Omron CX-Programmer project 新工程 (CX-Programmer 9.50)

# PLC 新PLC1: CP1H X

## Global symbols (name address type ; comment)
0 CHANNEL  ; 重复
1 CHANNEL  ; 完成
1635 CHANNEL  ; 要校验数据开始地址
A392.05 BOOL  ; 串口2就绪
A392.06 BOOL  ; 串口2接收完成
A393 CHANNEL  ; 接收计数器
A526.00 BOOL  ; 复位串口2
D1000 CHANNEL  ; 发送控制字
D1001 CHANNEL  ; 发送字节数
D1002 CHANNEL  ; 站号、功能码
D1003 CHANNEL  ; 寄存器开始地址
D1004 CHANNEL  ; 数据量
D1300 CHANNEL  ; 控制数据
D1301 CHANNEL  ; 收回的字节数
D1315 CHANNEL  ; 备份写数据
D1600 CHANNEL  ; 温度PV首地址
D1605 CHANNEL  ; 输出限位手动参数地址
D1610 CHANNEL  ; 检查结果0
D1611 CHANNEL  ; 检查结果1
D1612 CHANNEL  ; 检查结果2
D1613 CHANNEL  ; 检查结果3
D1614 CHANNEL  ; 检查结果4
D1615 CHANNEL  ; 检查结果5
D1616 CHANNEL  ; 检查结果6
D1617 CHANNEL  ; 结果2
D1618 CHANNEL  ; 缓存
D1619 CHANNEL  ; 检查中止操作位
D1620 CHANNEL  ; 通道
D1621 CHANNEL  ; 缓存
D1622 CHANNEL  ; 缓存
D1623 CHANNEL  ; 数据一致
D1624 CHANNEL  ; 比较开始地址1
D1625 CHANNEL  ; 比较开始地址2
D1626 CHANNEL  ; 比较结果地址
D1627 CHANNEL  ; 比较结果2
D1628 CHANNEL  ; 比较结果3
D1629 CHANNEL  ; 比较结果4
D1630 CHANNEL  ; 通信状态
D1631 CHANNEL  ; 模块类型
D1632 CHANNEL  ; 延时计数
D1633 CHANNEL  ; 通信故障计数器
D1634 CHANNEL  ; 要校验数据长度
D1635 CHANNEL  ; 要校验的数据首地址
D1636 CHANNEL  ; CRC高字节
D1637 CHANNEL  ; CRC低字节
D1638 CHANNEL  ; CRC结果
D1640 CHANNEL  ; 启动控制地址
D1641 CHANNEL  ; 启动控制缓存地址
D1642 CHANNEL  ; 通信计数器地址
D1643 CHANNEL  ; 故障计数器地址
D1644 CHANNEL  ; 通信计数器地址
D1645 CHANNEL  ; 通信故障计数器地址
D1646 CHANNEL  ; SV缓存首地址
D1647 CHANNEL  ; Pb缓存首地址
D1648 CHANNEL  ; 启动停止缓存地址
D1649 CHANNEL  ; 整定缓存地址
D1650 CHANNEL  ; 模块站号
D1651 CHANNEL  ; 参数开始地址
D1652 CHANNEL  ; 通信错误码
D1653 CHANNEL  ; 站切换状态
D1654 CHANNEL  ; 间隔计数
D1956 CHANNEL  ; 指针1
D1957 CHANNEL  ; 指针2
D1958 CHANNEL  ; 计数
D1960 CHANNEL  ; 缓存
D1961 CHANNEL  ; 计算的字节
D1962 CHANNEL  ; 高字节
D20000 CHANNEL  ; 发送控制字
D20001 CHANNEL  ; 发送字节数
D20002 CHANNEL  ; 站号、功能码
D20003 CHANNEL  ; 开始地址
D20004 CHANNEL  ; 字数
D20138 CHANNEL  ; CRC结果
D20300 CHANNEL  ; 控制数据
D20301 CHANNEL  ; 收回的字节数
D20315 CHANNEL  ; 备份数据
D20610 CHANNEL  ; 比较结果1
D20611 CHANNEL  ; 比较结果2
D20612 CHANNEL  ; 比较结果3
D20623 CHANNEL  ; 数据一致
D20624 CHANNEL  ; 比较开始地址1
D20625 CHANNEL  ; 比较开始地址2
D20630 CHANNEL  ; 通信状态
D20632 CHANNEL  ; 延时计数
D20633 CHANNEL  ; 通信故障计数
D20634 CHANNEL  ; 校验数据长度
D20635 CHANNEL  ; 校验数据源地址
D20636 CHANNEL  ; CRC高字节
D20637 CHANNEL  ; CRC低字节
D20638 CHANNEL  ; CRC结果
D20640 CHANNEL  ; 启停参数地址
D20641 CHANNEL  ; 启停参数缓存地址
D20642 CHANNEL  ; 通信计数地址
D20643 CHANNEL  ; 通信故障计数地址
D20650 CHANNEL  ; 站号变量
D20651 CHANNEL  ; 数据存放变量
D20653 CHANNEL  ; 站号切换状态
D20654 CHANNEL  ; 通信间隔
D20655 CHANNEL  ; 缓存
D2074 CHANNEL  ; 模块1读Pb记录
D20956 CHANNEL  ; 指针1
D20957 CHANNEL  ; 指针2
D20958 CHANNEL  ; 计数
D20960 CHANNEL  ; 缓存
D20961 CHANNEL  ; 计算的字节
D2274 CHANNEL  ; 模块2读Pb记录
T0200 BOOL  ; 读温度超时
T0201 BOOL  ; 读输出限位超时
T0202 BOOL  ; 写参数超时
T0203 BOOL  ; 写手动、输出限位超时
T0204 BOOL  ; 写整定超时
W20.00 BOOL  ; CRC校验错误
W20.01 BOOL  ; 读输出CRC错误
W20.02 BOOL  ; 写模块校验错误
W20.10 BOOL  ; 通信完成
W21.00 BOOL  ; 启动通信
W22.00 BOOL  ; 发送读温度消息
W22.01 BOOL  ; 发送写参数消息
W22.02 BOOL  ; 发整定消息
W22.03 BOOL  ; 发送读Pb消息
W22.04 BOOL  ; 发送写Pb消息
W22.05 BOOL  ; 接收数据处理
W22.06 BOOL  ; 发送写参数消息
W22.07 BOOL  ; 检查接收是否完成
W22.08 BOOL  ; 接收数据处理
W22.09 BOOL  ; 写手动输出准备
W22.10 BOOL  ; 检查接收完成
W22.11 BOOL  ; 接收数据处理
W22.12 BOOL  ; 写手动输出限位
W22.13 BOOL  ; 检查接收完成
W22.14 BOOL  ; 接收数据处理

## Program BD4543通信 (cyclic task 0)
Local symbols
CRC余数表 D1700 WORD  ; CRC余数表
的630 UINT

### Section 调信主程序

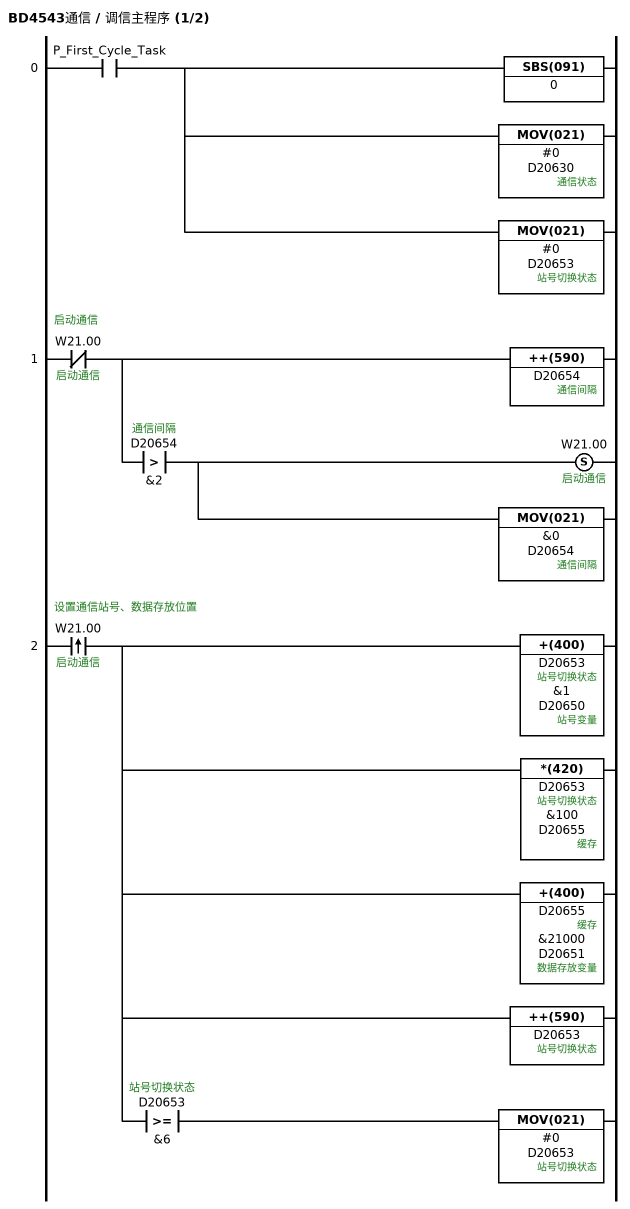
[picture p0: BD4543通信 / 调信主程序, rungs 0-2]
; rung 0
LD P_First_Cycle_Task
SBS(091) 0  // 初始化
MOV(021) #0 D20630  ; 通信状态
MOV(021) #0 D20653  ; 站号切换状态
; rung 1: 启动通信
LDNOT W21.00  ; 启动通信
++(590) D20654  ; 通信间隔
AND>(320) D20654 &2  ; 通信间隔
SET W21.00  ; 启动通信
MOV(021) &0 D20654  ; 通信间隔
; rung 2: 设置通信站号、数据存放位置
@LD W21.00  ; 启动通信
+(400) D20653 &1 D20650  ; 站号切换状态, 站号变量
*(420) D20653 &100 D20655  ; 站号切换状态, 缓存
+(400) D20655 &21000 D20651  ; 缓存, 数据存放变量
++(590) D20653  ; 站号切换状态
AND>=(325) D20653 &6  ; 站号切换状态
MOV(021) #0 D20653  ; 站号切换状态

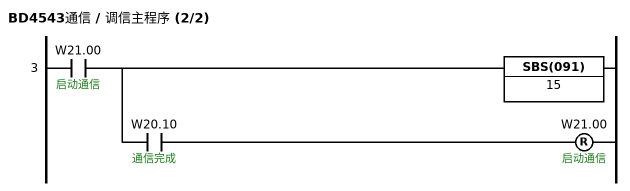
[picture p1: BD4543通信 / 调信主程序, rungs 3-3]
; rung 3
LD W21.00  ; 启动通信
SBS(091) 15
AND W20.10  ; 通信完成
RSET W21.00  ; 启动通信

### Section 通信状态处理15

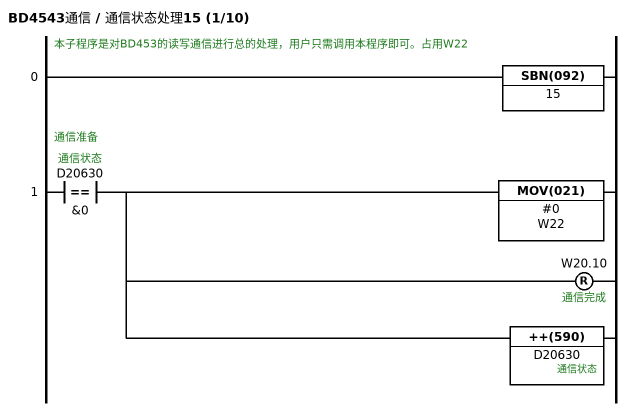
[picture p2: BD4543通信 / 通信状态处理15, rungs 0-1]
; rung 0: 本子程序是对BD453的读写通信进行总的处理，用户只需调用本程序即可。占用W22
SBN(092) 15
; rung 1: 通信准备
LD=(300) D20630 &0  ; 通信状态
MOV(021) #0 W22
RSET W20.10  ; 通信完成
++(590) D20630  ; 通信状态

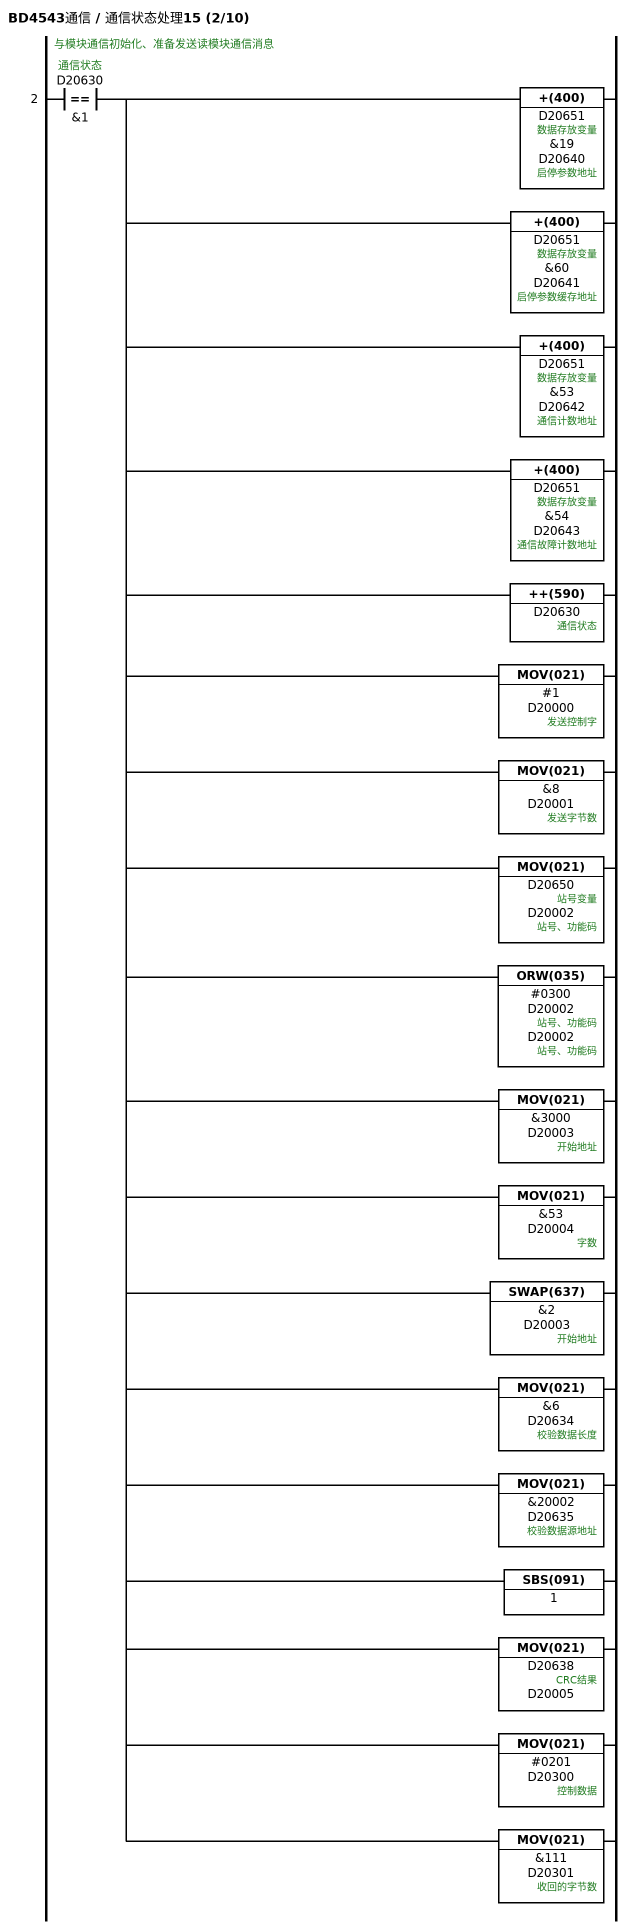
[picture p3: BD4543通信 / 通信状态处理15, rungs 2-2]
; rung 2: 与模块通信初始化、准备发送读模块通信消息
LD=(300) D20630 &1  ; 通信状态
+(400) D20651 &19 D20640  ; 数据存放变量, 启停参数地址
+(400) D20651 &60 D20641  ; 数据存放变量, 启停参数缓存地址
+(400) D20651 &53 D20642  ; 数据存放变量, 通信计数地址
+(400) D20651 &54 D20643  ; 数据存放变量, 通信故障计数地址
++(590) D20630  ; 通信状态
MOV(021) #1 D20000  ; 发送控制字
MOV(021) &8 D20001  ; 发送字节数
MOV(021) D20650 D20002  ; 站号变量, 站号、功能码
ORW(035) #0300 D20002 D20002  ; 站号、功能码
MOV(021) &3000 D20003  ; 开始地址
MOV(021) &53 D20004  ; 字数
SWAP(637) &2 D20003  ; 开始地址
MOV(021) &6 D20634  ; 校验数据长度
MOV(021) &20002 D20635  ; 校验数据源地址
SBS(091) 1
MOV(021) D20638 D20005  ; CRC结果
MOV(021) #0201 D20300  ; 控制数据
MOV(021) &111 D20301  ; 收回的字节数

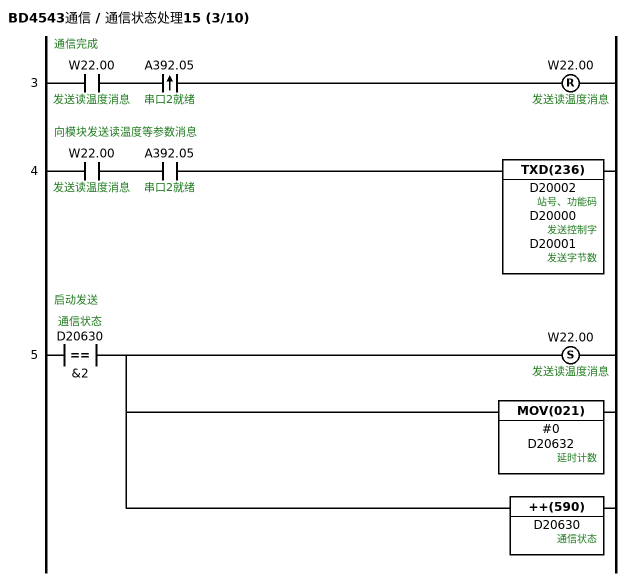
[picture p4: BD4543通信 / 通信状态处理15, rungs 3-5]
; rung 3: 通信完成
LD W22.00  ; 发送读温度消息
@AND A392.05  ; 串口2就绪
RSET W22.00  ; 发送读温度消息
; rung 4: 向模块发送读温度等参数消息
LD W22.00  ; 发送读温度消息
AND A392.05  ; 串口2就绪
TXD(236) D20002 D20000 D20001  ; 站号、功能码, 发送控制字, 发送字节数
; rung 5: 启动发送
LD=(300) D20630 &2  ; 通信状态
SET W22.00  ; 发送读温度消息
MOV(021) #0 D20632  ; 延时计数
++(590) D20630  ; 通信状态

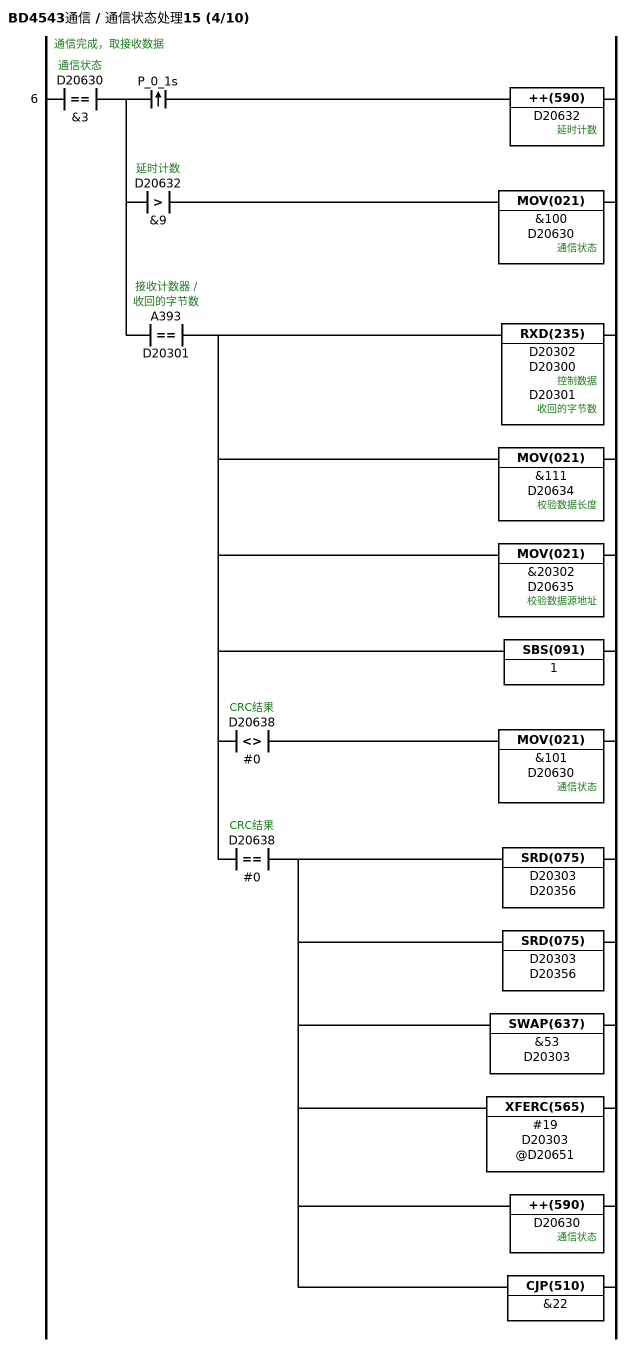
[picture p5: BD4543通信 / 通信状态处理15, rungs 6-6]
; rung 6: 通信完成，取接收数据
LD=(300) D20630 &3  ; 通信状态
OUT TR0
@AND P_0_1s
++(590) D20632  ; 延时计数
LD TR0
AND>(320) D20632 &9  ; 延时计数
MOV(021) &100 D20630  ; 通信状态
LD TR0
AND=(300) A393 D20301  ; 接收计数器, 收回的字节数
OUT TR0
RXD(235) D20302 D20300 D20301  ; 控制数据, 收回的字节数
MOV(021) &111 D20634  ; 校验数据长度
MOV(021) &20302 D20635  ; 校验数据源地址
SBS(091) 1
AND<>(305) D20638 #0  ; CRC结果
MOV(021) &101 D20630  ; 通信状态
LD TR0
AND=(300) D20638 #0  ; CRC结果
SRD(075) D20303 D20356
SRD(075) D20303 D20356
SWAP(637) &53 D20303
XFERC(565) #19 D20303 @D20651
++(590) D20630  ; 通信状态
CJP(510) &22

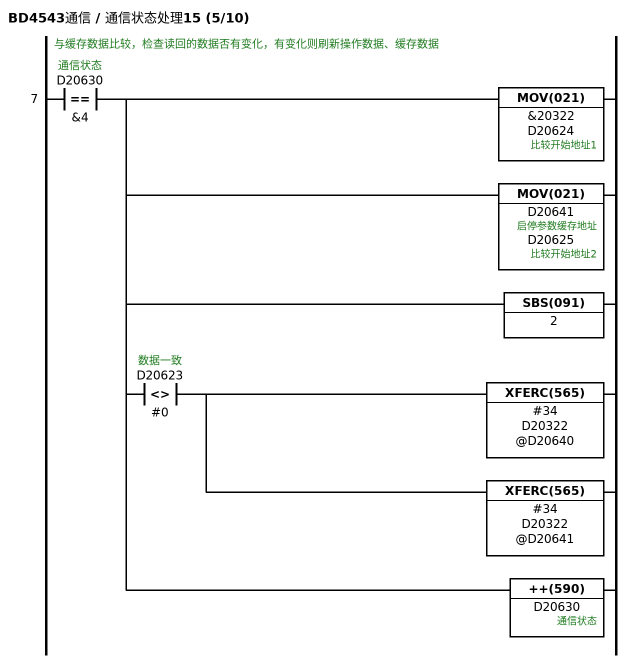
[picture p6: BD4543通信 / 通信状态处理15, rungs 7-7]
; rung 7: 与缓存数据比较，检查读回的数据否有变化，有变化则刷新操作数据、缓存数据
LD=(300) D20630 &4  ; 通信状态
OUT TR0
MOV(021) &20322 D20624  ; 比较开始地址1
MOV(021) D20641 D20625  ; 启停参数缓存地址, 比较开始地址2
SBS(091) 2
AND<>(305) D20623 #0  ; 数据一致
XFERC(565) #34 D20322 @D20640
XFERC(565) #34 D20322 @D20641
LD TR0
++(590) D20630  ; 通信状态

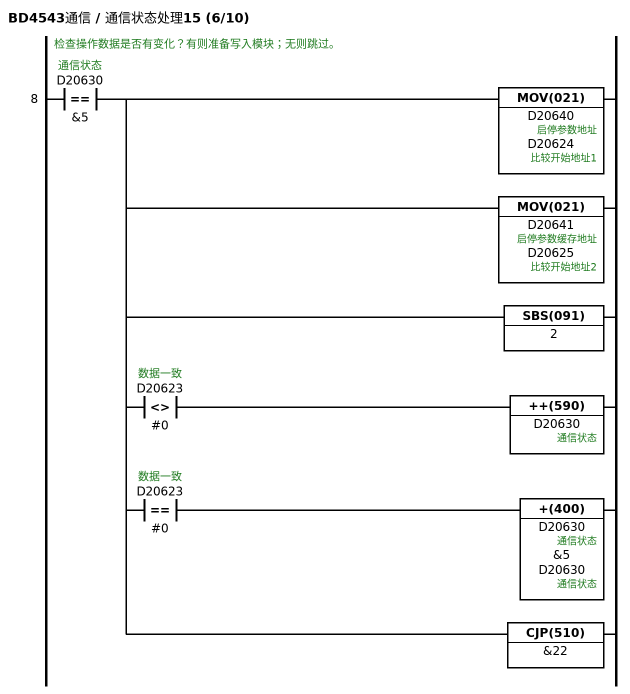
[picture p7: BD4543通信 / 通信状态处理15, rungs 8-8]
; rung 8: 检查操作数据是否有变化？有则准备写入模块；无则跳过。
LD=(300) D20630 &5  ; 通信状态
OUT TR0
MOV(021) D20640 D20624  ; 启停参数地址, 比较开始地址1
MOV(021) D20641 D20625  ; 启停参数缓存地址, 比较开始地址2
SBS(091) 2
AND<>(305) D20623 #0  ; 数据一致
++(590) D20630  ; 通信状态
LD TR0
AND=(300) D20623 #0  ; 数据一致
+(400) D20630 &5 D20630  ; 通信状态
LD TR0
CJP(510) &22

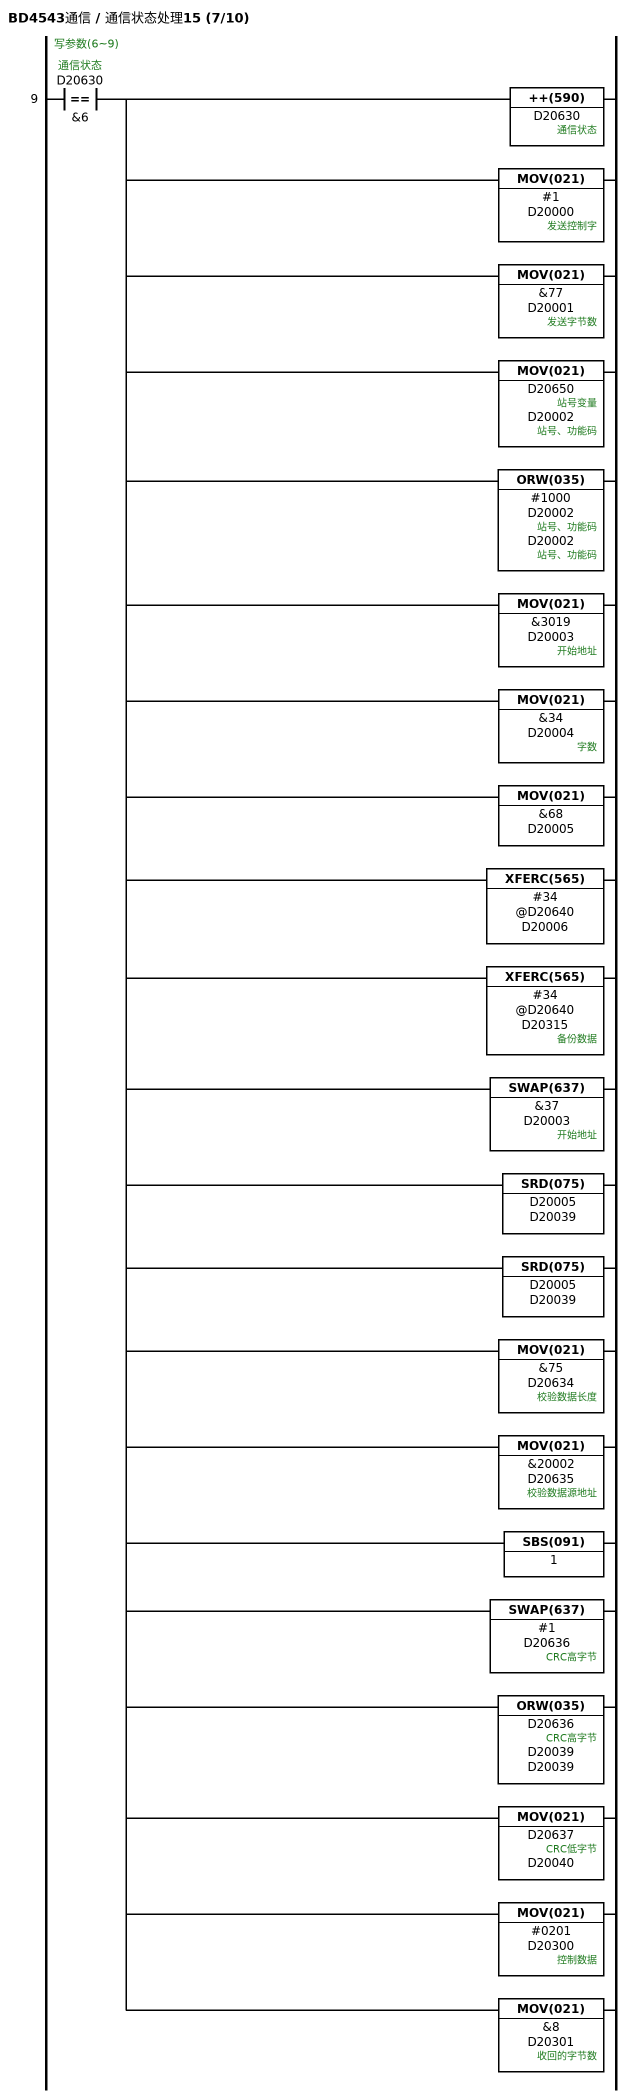
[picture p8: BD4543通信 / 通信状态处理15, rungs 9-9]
; rung 9: 写参数(6~9)
LD=(300) D20630 &6  ; 通信状态
++(590) D20630  ; 通信状态
MOV(021) #1 D20000  ; 发送控制字
MOV(021) &77 D20001  ; 发送字节数
MOV(021) D20650 D20002  ; 站号变量, 站号、功能码
ORW(035) #1000 D20002 D20002  ; 站号、功能码
MOV(021) &3019 D20003  ; 开始地址
MOV(021) &34 D20004  ; 字数
MOV(021) &68 D20005
XFERC(565) #34 @D20640 D20006
XFERC(565) #34 @D20640 D20315  ; 备份数据
SWAP(637) &37 D20003  ; 开始地址
SRD(075) D20005 D20039
SRD(075) D20005 D20039
MOV(021) &75 D20634  ; 校验数据长度
MOV(021) &20002 D20635  ; 校验数据源地址
SBS(091) 1
SWAP(637) #1 D20636  ; CRC高字节
ORW(035) D20636 D20039 D20039  ; CRC高字节
MOV(021) D20637 D20040  ; CRC低字节
MOV(021) #0201 D20300  ; 控制数据
MOV(021) &8 D20301  ; 收回的字节数

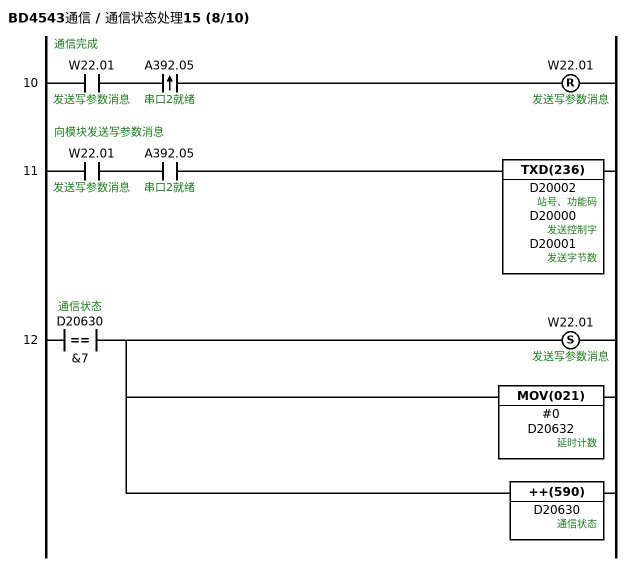
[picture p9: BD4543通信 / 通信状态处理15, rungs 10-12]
; rung 10: 通信完成
LD W22.01  ; 发送写参数消息
@AND A392.05  ; 串口2就绪
RSET W22.01  ; 发送写参数消息
; rung 11: 向模块发送写参数消息
LD W22.01  ; 发送写参数消息
AND A392.05  ; 串口2就绪
TXD(236) D20002 D20000 D20001  ; 站号、功能码, 发送控制字, 发送字节数
; rung 12
LD=(300) D20630 &7  ; 通信状态
SET W22.01  ; 发送写参数消息
MOV(021) #0 D20632  ; 延时计数
++(590) D20630  ; 通信状态

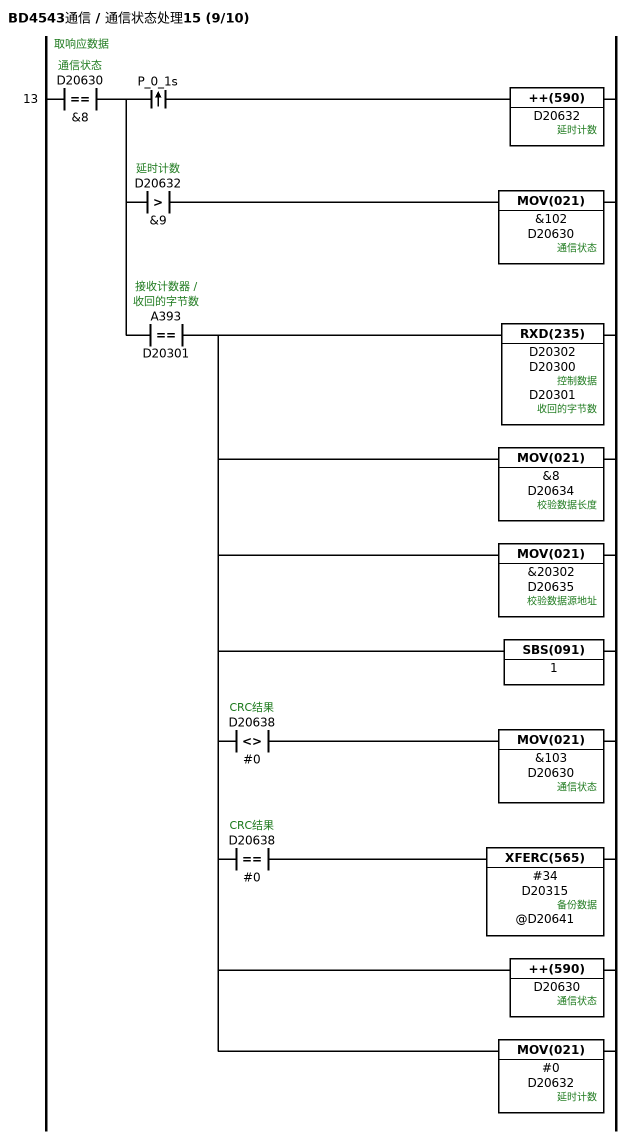
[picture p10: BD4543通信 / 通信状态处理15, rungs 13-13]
; rung 13: 取响应数据
LD=(300) D20630 &8  ; 通信状态
OUT TR0
@AND P_0_1s
++(590) D20632  ; 延时计数
LD TR0
AND>(320) D20632 &9  ; 延时计数
MOV(021) &102 D20630  ; 通信状态
LD TR0
AND=(300) A393 D20301  ; 接收计数器, 收回的字节数
OUT TR0
RXD(235) D20302 D20300 D20301  ; 控制数据, 收回的字节数
MOV(021) &8 D20634  ; 校验数据长度
MOV(021) &20302 D20635  ; 校验数据源地址
SBS(091) 1
AND<>(305) D20638 #0  ; CRC结果
MOV(021) &103 D20630  ; 通信状态
LD TR0
AND=(300) D20638 #0  ; CRC结果
XFERC(565) #34 D20315 @D20641  ; 备份数据
LD TR0
++(590) D20630  ; 通信状态
MOV(021) #0 D20632  ; 延时计数

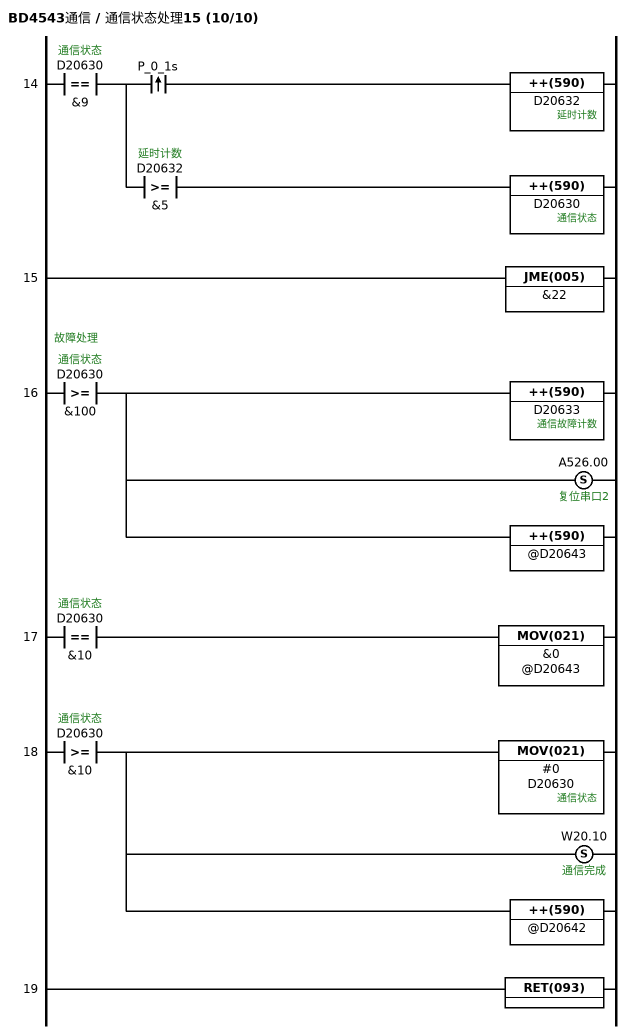
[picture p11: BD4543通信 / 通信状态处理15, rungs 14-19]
; rung 14
LD=(300) D20630 &9  ; 通信状态
OUT TR0
@AND P_0_1s
++(590) D20632  ; 延时计数
LD TR0
AND>=(325) D20632 &5  ; 延时计数
++(590) D20630  ; 通信状态
; rung 15
JME(005) &22
; rung 16: 故障处理
LD>=(325) D20630 &100  ; 通信状态
++(590) D20633  ; 通信故障计数
SET A526.00  ; 复位串口2
++(590) @D20643
; rung 17
LD=(300) D20630 &10  ; 通信状态
MOV(021) &0 @D20643
; rung 18
LD>=(325) D20630 &10  ; 通信状态
MOV(021) #0 D20630  ; 通信状态
SET W20.10  ; 通信完成
++(590) @D20642
; rung 19
RET(093)

### Section 通信初始化0

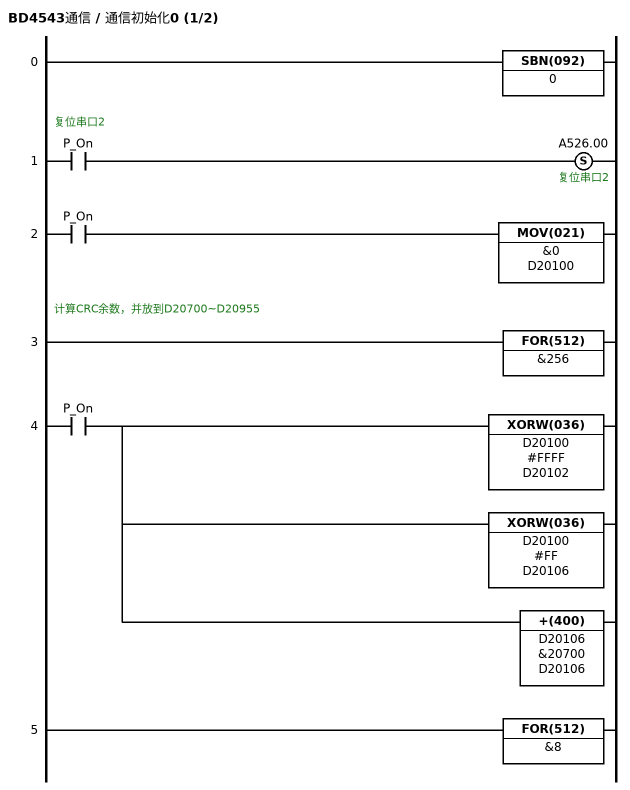
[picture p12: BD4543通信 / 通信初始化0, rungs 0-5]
; rung 0
SBN(092) 0
; rung 1: 复位串口2
LD P_On
SET A526.00  ; 复位串口2
; rung 2
LD P_On
MOV(021) &0 D20100
; rung 3: 计算CRC余数，并放到D20700~D20955
FOR(512) &256
; rung 4
LD P_On
XORW(036) D20100 #FFFF D20102
XORW(036) D20100 #FF D20106
+(400) D20106 &20700 D20106
; rung 5
FOR(512) &8

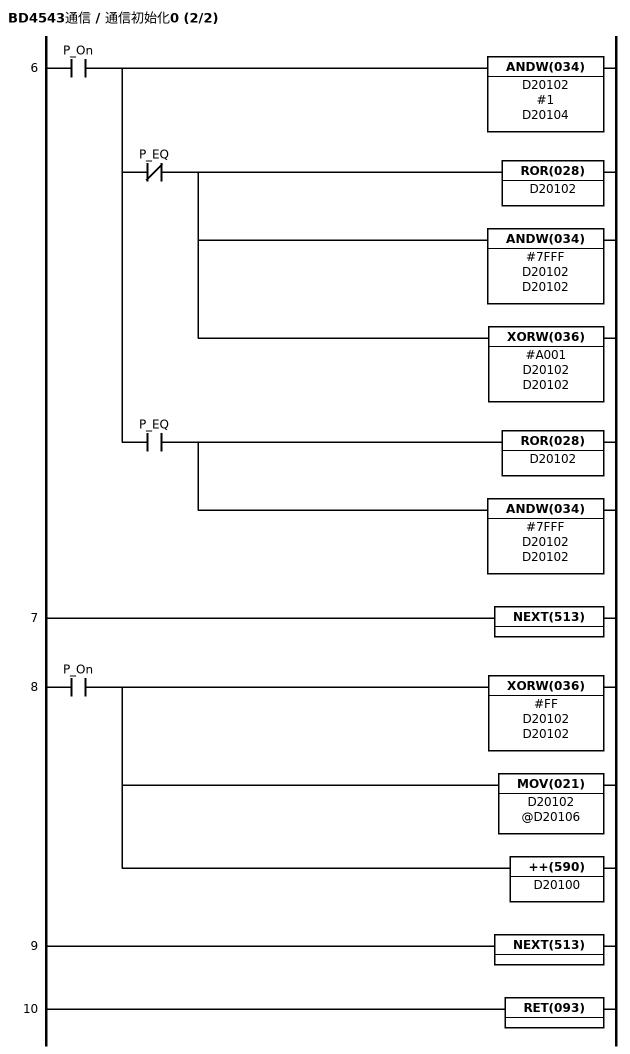
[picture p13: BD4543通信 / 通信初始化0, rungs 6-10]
; rung 6
LD P_On
OUT TR0
ANDW(034) D20102 #1 D20104
ANDNOT P_EQ
ROR(028) D20102
ANDW(034) #7FFF D20102 D20102
XORW(036) #A001 D20102 D20102
LD TR0
AND P_EQ
ROR(028) D20102
ANDW(034) #7FFF D20102 D20102
; rung 7
NEXT(513)
; rung 8
LD P_On
XORW(036) #FF D20102 D20102
MOV(021) D20102 @D20106
++(590) D20100
; rung 9
NEXT(513)
; rung 10
RET(093)

### Section 检查数据一致2
; 数据源地址D1624、D1625、字数D1626、数据变化D1627，=0无变化

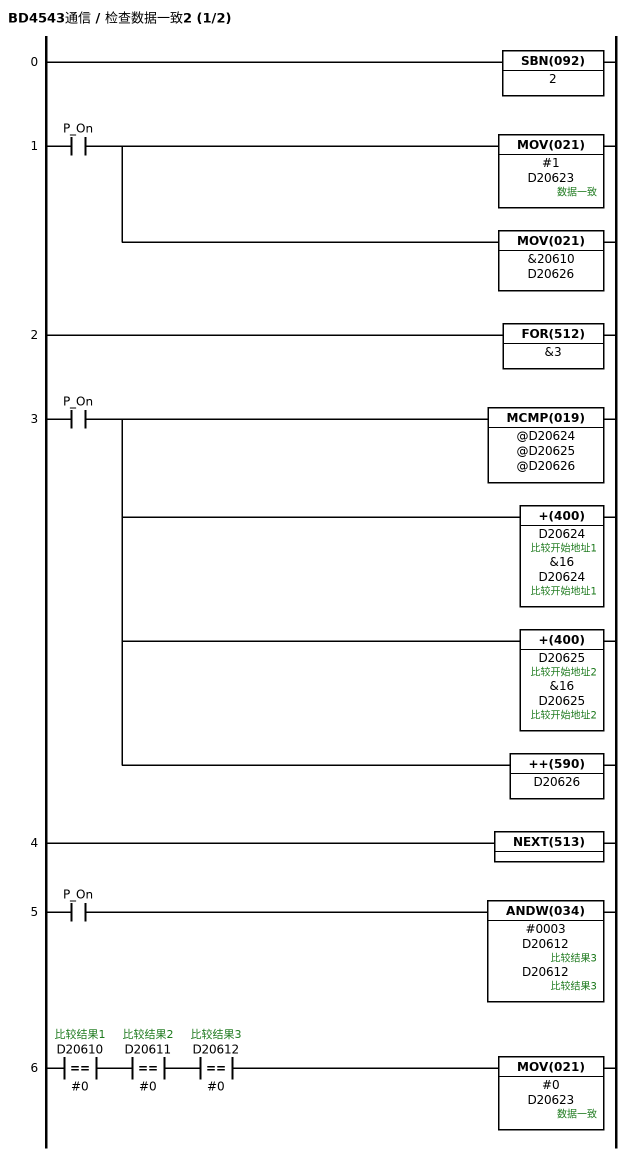
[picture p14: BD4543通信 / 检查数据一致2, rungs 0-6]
; rung 0
SBN(092) 2
; rung 1
LD P_On
MOV(021) #1 D20623  ; 数据一致
MOV(021) &20610 D20626
; rung 2
FOR(512) &3
; rung 3
LD P_On
MCMP(019) @D20624 @D20625 @D20626
+(400) D20624 &16 D20624  ; 比较开始地址1
+(400) D20625 &16 D20625  ; 比较开始地址2
++(590) D20626
; rung 4
NEXT(513)
; rung 5
LD P_On
ANDW(034) #0003 D20612 D20612  ; 比较结果3
; rung 6
LD=(300) D20610 #0  ; 比较结果1
AND=(300) D20611 #0  ; 比较结果2
AND=(300) D20612 #0  ; 比较结果3
MOV(021) #0 D20623  ; 数据一致

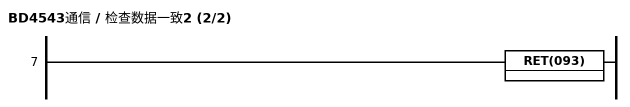
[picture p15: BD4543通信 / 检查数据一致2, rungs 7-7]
; rung 7
RET(093)

### Section CRC校验1
; D1634 需要校验的数据长度、D1635 需要校验的数据首地址，结果：D1636CRC高字节、D1637CRC低字节

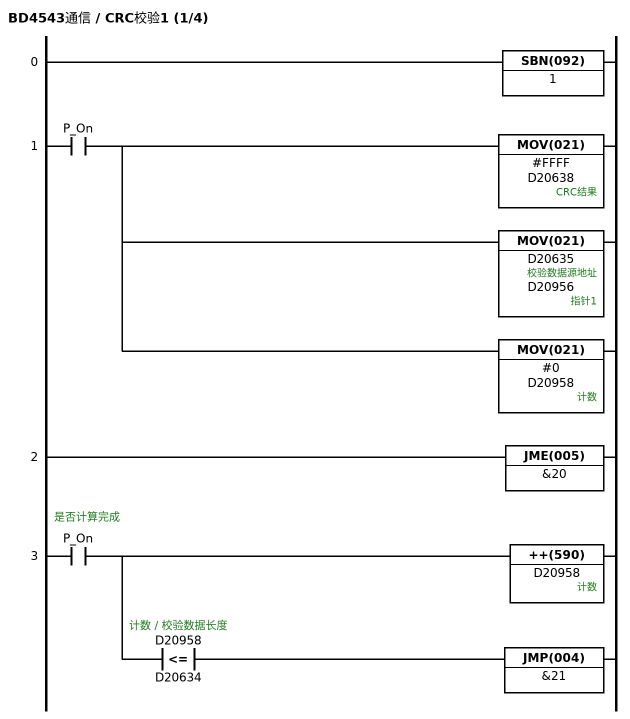
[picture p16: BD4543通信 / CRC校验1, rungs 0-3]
; rung 0
SBN(092) 1
; rung 1
LD P_On
MOV(021) #FFFF D20638  ; CRC结果
MOV(021) D20635 D20956  ; 校验数据源地址, 指针1
MOV(021) #0 D20958  ; 计数
; rung 2
JME(005) &20
; rung 3: 是否计算完成
LD P_On
++(590) D20958  ; 计数
AND<=(315) D20958 D20634  ; 计数, 校验数据长度
JMP(004) &21

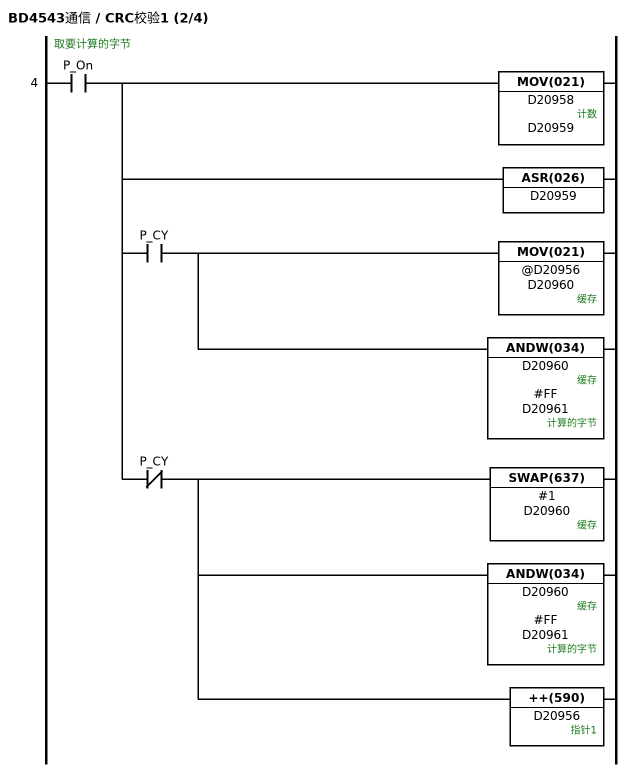
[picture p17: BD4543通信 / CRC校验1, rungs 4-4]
; rung 4: 取要计算的字节
LD P_On
OUT TR0
MOV(021) D20958 D20959  ; 计数
ASR(026) D20959
AND P_CY
MOV(021) @D20956 D20960  ; 缓存
ANDW(034) D20960 #FF D20961  ; 缓存, 计算的字节
LD TR0
ANDNOT P_CY
SWAP(637) #1 D20960  ; 缓存
ANDW(034) D20960 #FF D20961  ; 缓存, 计算的字节
++(590) D20956  ; 指针1

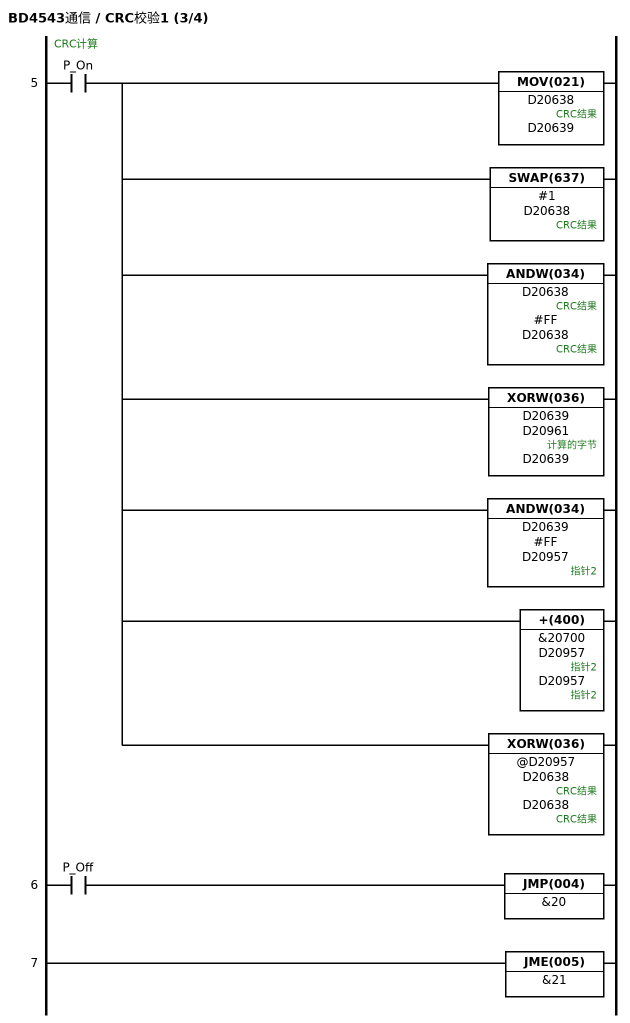
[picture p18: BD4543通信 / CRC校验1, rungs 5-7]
; rung 5: CRC计算
LD P_On
MOV(021) D20638 D20639  ; CRC结果
SWAP(637) #1 D20638  ; CRC结果
ANDW(034) D20638 #FF D20638  ; CRC结果
XORW(036) D20639 D20961 D20639  ; 计算的字节
ANDW(034) D20639 #FF D20957  ; 指针2
+(400) &20700 D20957 D20957  ; 指针2
XORW(036) @D20957 D20638 D20638  ; CRC结果
; rung 6
LD P_Off
JMP(004) &20
; rung 7
JME(005) &21

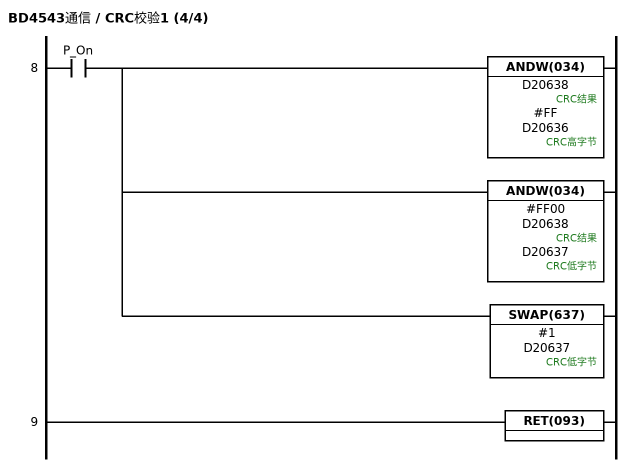
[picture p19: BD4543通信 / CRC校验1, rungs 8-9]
; rung 8
LD P_On
ANDW(034) D20638 #FF D20636  ; CRC结果, CRC高字节
ANDW(034) #FF00 D20638 D20637  ; CRC结果, CRC低字节
SWAP(637) #1 D20637  ; CRC低字节
; rung 9
RET(093)

### Section END
; rung 0
END(001)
